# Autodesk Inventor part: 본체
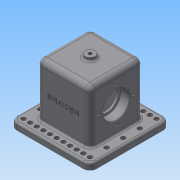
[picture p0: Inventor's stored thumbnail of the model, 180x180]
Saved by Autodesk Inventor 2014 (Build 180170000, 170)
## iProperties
Created: 2018-11
Part Number: 본체
Material: 일반
Document SubType Name: Modeling
Designer: NET
Density: 1 g/cm^3
Appearance: 기본값
Mass: 376.663 g
Surface Area: 777.082 cm^2
Volume: 376.663 cm^3
Author: NET
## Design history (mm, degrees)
sketch "스케치1"
  geometry: L1 (60, -60)-(-60, -60); L2 (-60, -60)-(-60, 60); L3 (-60, 60)-(60, 60); L4 (60, 60)-(60, -60); 3 further points
  constraints: 8 end point, 2 midpoint, 2 parallel, 1 horizontal, 1 horizontal alignment, 1 perpendicular, 1 vertical alignment
  dimensions: "d0" = 120 distance of L2.end L3.end; "d1" = 120 distance of L3.end L1.start
extrude "돌출1" new body sketch "스케치1" distance "d2" = 10; taper "d3" = 0 deg
sketch "스케치2"
  geometry: L1 (-40, 40)-(40, 40); L2 (40, 40)-(40, -40); L3 (40, -40)-(-40, -40); L4 (-40, -40)-(-40, 40); 3 further points
  constraints: 8 end point, 2 midpoint, 2 parallel, 2 perpendicular, 1 horizontal, 1 horizontal alignment, 1 vertical alignment
  dimensions: "d4" = 80 distance of L1.start L1.end
extrude "돌출2" join sketch "스케치2" distance "d5" = 80; taper "d6" = 0 deg
node "작업 평면1"
sketch "스케치3"
  geometry: C1 r 7.5 at (0, 0); 1 further point
  constraints: 1 centre point, 1 coincident
  dimensions: "d8" = 15 diameter of C1
extrude "돌출3" join sketch "스케치3" stored distance "d9" = 80; taper "d10" = 0 deg
sketch "스케치4"
  geometry: L1 (60, 60)-(-60, 60) reference; L2 (-23, 30)-(23, 30); L3 (23, 30)-(23, -30); L4 (23, -30)-(-23, -30); L5 (-23, -30)-(-23, 30); 4 further points
  constraints: 8 end point, 3 midpoint, 2 parallel, 1 horizontal, 1 horizontal alignment, 1 perpendicular, 1 vertical alignment
  dimensions: "d11" = 46 distance of L3.end L4.end; "d12" = 60 distance of L2.end L3.end
extrude "돌출4" cut sketch "스케치4" distance "d13" = 80; taper "d14" = 0 deg
sketch "스케치5"
  geometry: C1 r 7.5 at (0, 0) reference; 1 further point
  constraints: 1 coincident
hole "구멍1" sketch "스케치5" at (0, 0) diameter "d15" = 4.917; stored, may be unused: countersink angle "d19" = 90 deg, drill point angle "d21" = 0 deg; dims "d16" = 6, "d17" = 4, "d18" = 2, "d20" = 8
sketch "스케치6"
  geometry: L1 (-40, 48)-(-23, 48); L2 (-60, 0)-(60, 0) reference; L3 (-40, 10)-(-40, 90) reference; L4 (-40, 48)-(-40, 68); L5 (-40, 68)-(-26, 68); L6 (-26, 68)-(-26, 64.5); L7 (-26, 64.5)-(-23, 64.5); L8 (-23, 64.5)-(-23, 48); 1 further point
  constraints: 12 end point, 4 perpendicular, 2 point on line, 1 horizontal
  dimensions: "d24" = 48 distance from line of L2 L1.end; "d25" = 40 diameter of L4.end L1; "d26" = 14 distance of L4.end L5.end; "d27" = 33 diameter of L6.end L1; "d28" = 3 distance of L6.end L7.end
revolve "회전1" sketch "스케치6" stored, may be unused: angle "d29" = 90 deg
sketch "스케치7" dims "d30" = 52
  geometry: C1 r 20 at (40, 38) reference; 6 further points
  constraints: 2 vertical alignment, 1 coincident, 7 other
  dimensions: "d33" = 360 deg dimension on C1.centre point (40, 64) (derived)
hole "구멍2" sketch "스케치7" at (40, 64), (14, 38), (40, 12), (66, 38) diameter "d35" = 3.242; stored, may be unused: countersink angle "d39" = 90 deg, drill point angle "d41" = 118 deg; dims "d36" = 8, "d37" = 4, "d38" = 2, "d40" = 10
fillet "모깎기1" dims "d42" = 0.6
chamfer "모따기1" distance "d43" = 1; stored, may be unused: second distance "d44" = 2, angle "d45" = 45 deg
fillet "모깎기2" dims "d46" = 8
fillet "모깎기3" dims "d47" = 3
fillet "모깎기4" dims "d48" = 10
fillet "모깎기5" dims "d49" = 3
sketch "스케치8" dims "d52" = 10, "d62" = 10
  geometry: L1 (57, 50)-(57, -50) reference; L2 (-50, 57)-(50, 57) reference; L3 (-57, -50)-(-57, 50) reference; L4 (50, -57)-(-50, -57) reference; L5 (0, 57)-(0, -57); L6 (-57, 0)-(57, 0); A1 r 7 centre (-50, 50) between (-50, 57) and (-57, 50) reference; 32 further points
  constraints: 16 symmetric about line, 6 midpoint, 4 end point, 1 coincident, 1 horizontal, 1 vertical, 13 other
  dimensions: "d55" = 25 distance of point (-50, 50) point (-50, 25); "d59" = 10 distance of point (-50, 50) point (-40, 50)
hole "구멍3" sketch "스케치8" diameter "d64" = 6.6; stored, may be unused: countersink angle "d68" = 90 deg, drill point angle "d70" = 118 deg; dims "d65" = 8, "d66" = 4, "d67" = 2, "d69" = 10
sketch "스케치9"
  geometry: L1 (92, -82)-(82, -82) reference; L2 (64, 8)-(0, 8) reference; 3 further points
  constraints: 1 midpoint, 1 vertical alignment, 1 other
  dimensions: "d71" = 48 distance from line of L1 point (32, -34)
feature "엠보싱1" sketch "스케치9" dims "d0" = 120, "d1" = 120, "d72" = 0.5, "d73" = 0
node "솔리드1"
mirror "대칭1"
mirror "대칭2"
other parameters: "d7" = -95
